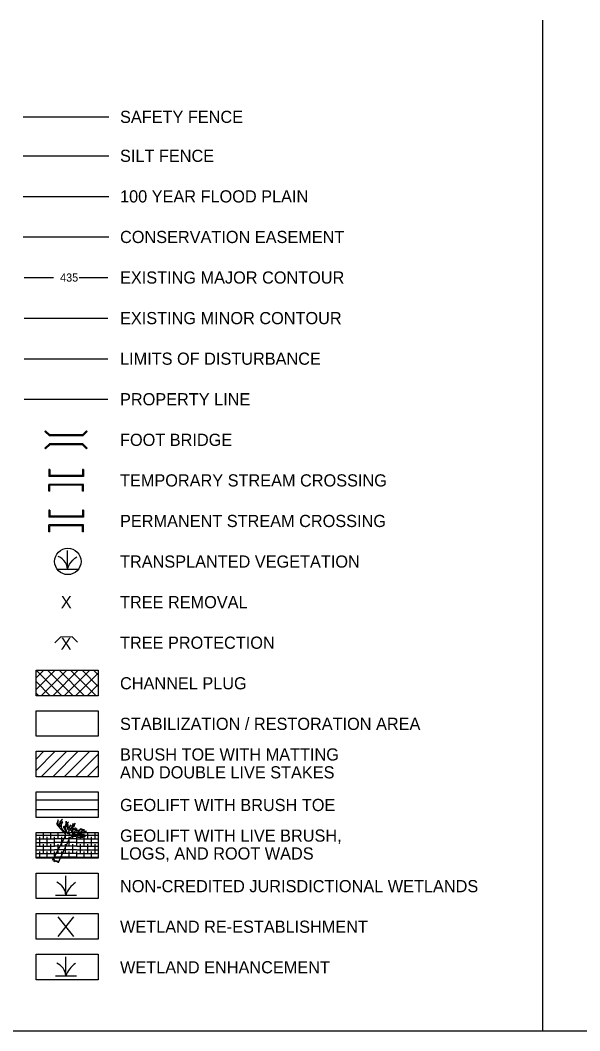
# Model space of a CAD drawing. Extents: x 1577194 to 26153757, y 723342 to 3772486.
# Drawn here: x 1577622 to 1577967, y 724102 to 724725 of the extents above; entities that cross this region are included whole.
import ezdxf

# ---------------------------------------------------------------- set-up
doc = ezdxf.new("R2010")
doc.units = 0
for name, color, linetype in [('Exist Hydro Swamp or Marsh', 7, 'Continuous'), ('G-ANNO-SYMB', 7, 'Continuous'), ('L-CL', 7, 'Continuous')]:
    doc.layers.add(name, color=color, linetype=linetype)

msp = doc.modelspace()

# ---------------------------------------------------------------- linework, layer by layer
at = {"layer": 'Exist Hydro Swamp or Marsh'}
for p, q in [((1577650.61, 724185.77), (1577650.61, 724197.6)), ((1577644.16, 724185.77), (1577650.61, 724185.77)), ((1577650.61, 724185.77), (1577657.06, 724185.77)), ((1577655.6, 724160.25), (1577645.75, 724172.23)), ((1577645.75, 724160.25), (1577655.6, 724172.23)), ((1577650.61, 724135.91), (1577650.61, 724147.75)), ((1577644.16, 724135.91), (1577650.61, 724135.91)), ((1577650.61, 724135.91), (1577657.06, 724135.91))]:
    msp.add_line(p, q, dxfattribs=at)
for centre, radius, start, end in [((1577641.41, 724185.1), 9.22, 4.14034, 67.53497), ((1577664.29, 724181.22), 14.42, 122.12745, 161.62219), ((1577641.41, 724135.24), 9.22, 4.14034, 67.53497), ((1577664.29, 724131.37), 14.42, 122.12745, 161.62219)]:
    msp.add_arc(centre, radius, start, end, dxfattribs=at)
at = {"layer": 'G-ANNO-SYMB'}
for points in [[(1577632.21, 724299.32), (1577670.57, 724299.32), (1577670.57, 724283.55), (1577632.21, 724283.55)], [(1577632.21, 724149.32), (1577670.57, 724149.32), (1577670.57, 724133.55), (1577632.21, 724133.55)]]:
    msp.add_lwpolyline(points, close=True, dxfattribs=at)
at = {"layer": 'L-CL'}
for p, q in [((1577944.13, 724724.8), (1577944.13, 724102.12)), ((1577624.31, 724665.25), (1577677.14, 724665.25)), ((1577624.31, 724641.25), (1577677.14, 724641.25)), ((1577624.31, 724616.25), (1577677.14, 724616.25)), ((1577624.31, 724591.25), (1577677.14, 724591.25)), ((1577624.99, 724566.25), (1577642.9, 724566.25)), ((1577658.73, 724566.25), (1577676.46, 724566.25)), ((1577624.99, 724541.25), (1577676.46, 724541.25)), ((1577624.99, 724516.25), (1577676.46, 724516.25)), ((1577624.99, 724491.25), (1577676.46, 724491.25)), ((1577638.09, 724471.84), (1577637.66, 724471.41)), ((1577640.42, 724468.66), (1577637.66, 724471.41)), ((1577640.67, 724469.27), (1577638.09, 724471.84)), ((1577661.03, 724468.69), (1577640.42, 724468.66)), ((1577660.78, 724469.3), (1577640.67, 724469.27)), ((1577663.35, 724471.88), (1577660.78, 724469.3)), ((1577663.78, 724471.45), (1577661.03, 724468.69)), ((1577663.35, 724471.88), (1577663.78, 724471.45)), ((1577640.43, 724463.8), (1577637.67, 724461.04)), ((1577637.67, 724461.04), (1577638.1, 724460.61)), ((1577640.68, 724463.2), (1577638.1, 724460.61)), ((1577661.03, 724463.83), (1577640.43, 724463.8)), ((1577660.78, 724463.22), (1577640.68, 724463.2)), ((1577663.36, 724460.65), (1577660.78, 724463.22)), ((1577663.79, 724461.08), (1577661.03, 724463.83)), ((1577663.79, 724461.08), (1577663.36, 724460.65)), ((1577640.67, 724447.93), (1577640.07, 724447.93)), ((1577640.07, 724447.93), (1577640.07, 724443.68)), ((1577661.39, 724443.68), (1577640.07, 724443.68)), ((1577640.67, 724447.93), (1577640.67, 724444.28)), ((1577660.78, 724444.28), (1577640.67, 724444.28)), ((1577660.78, 724447.93), (1577660.78, 724444.28)), ((1577661.39, 724447.93), (1577660.78, 724447.93)), ((1577661.39, 724447.93), (1577661.39, 724443.68)), ((1577661.39, 724438.82), (1577640.07, 724438.82)), ((1577640.07, 724434.56), (1577640.07, 724438.82)), ((1577660.78, 724438.21), (1577640.67, 724438.21)), ((1577640.67, 724434.56), (1577640.67, 724438.21)), ((1577660.78, 724434.56), (1577660.78, 724438.21)), ((1577661.39, 724434.56), (1577661.39, 724438.82)), ((1577640.67, 724434.56), (1577640.07, 724434.56)), ((1577661.39, 724434.56), (1577660.78, 724434.56)), ((1577640.67, 724422.93), (1577640.07, 724422.93)), ((1577640.07, 724422.93), (1577640.07, 724418.68)), ((1577661.39, 724418.68), (1577640.07, 724418.68)), ((1577640.67, 724422.93), (1577640.67, 724419.28)), ((1577660.78, 724419.28), (1577640.67, 724419.28)), ((1577660.78, 724422.93), (1577660.78, 724419.28)), ((1577661.39, 724422.93), (1577660.78, 724422.93)), ((1577661.39, 724422.93), (1577661.39, 724418.68)), ((1577661.39, 724413.82), (1577640.07, 724413.82)), ((1577640.07, 724409.56), (1577640.07, 724413.82)), ((1577660.78, 724413.21), (1577640.67, 724413.21)), ((1577640.67, 724409.56), (1577640.67, 724413.21)), ((1577660.78, 724409.56), (1577660.78, 724413.21)), ((1577661.39, 724409.56), (1577661.39, 724413.82)), ((1577640.67, 724409.56), (1577640.07, 724409.56)), ((1577661.39, 724409.56), (1577660.78, 724409.56)), ((1577632.21, 724319.52), (1577637.01, 724324.32)), ((1577632.21, 724312.45), (1577644.08, 724324.32)), ((1577632.26, 724324.32), (1577648.03, 724308.55)), ((1577635.39, 724308.55), (1577651.15, 724324.32)), ((1577639.33, 724324.32), (1577655.1, 724308.55)), ((1577642.46, 724308.55), (1577658.22, 724324.32)), ((1577646.4, 724324.32), (1577662.17, 724308.55)), ((1577649.53, 724308.55), (1577665.29, 724324.32)), ((1577653.47, 724324.32), (1577669.24, 724308.55)), ((1577660.54, 724324.32), (1577670.57, 724314.29)), ((1577667.61, 724324.32), (1577670.57, 724321.36)), ((1577656.6, 724308.55), (1577670.57, 724322.52)), ((1577632.21, 724317.3), (1577640.96, 724308.55)), ((1577663.67, 724308.55), (1577670.57, 724315.45)), ((1577632.21, 724310.22), (1577633.88, 724308.55)), ((1577632.21, 724269.52), (1577637.01, 724274.32)), ((1577632.21, 724262.45), (1577644.08, 724274.32)), ((1577635.39, 724258.55), (1577651.15, 724274.32)), ((1577642.46, 724258.55), (1577658.22, 724274.32)), ((1577649.53, 724258.55), (1577665.29, 724274.32)), ((1577656.6, 724258.55), (1577670.57, 724272.52)), ((1577663.67, 724258.55), (1577670.57, 724265.45)), ((1577632.21, 724244.43), (1577670.57, 724244.43)), ((1577632.21, 724238.43), (1577670.57, 724238.43)), ((1577645.94, 724232.07), (1577645.11, 724229.58)), ((1577645.82, 724229.4), (1577645.94, 724232.07)), ((1577646.83, 724230.94), (1577646.66, 724229.5)), ((1577648.59, 724232.43), (1577646.83, 724230.94)), ((1577647.19, 724229.65), (1577647.69, 724231.29)), ((1577648.75, 724230.86), (1577647.19, 724229.65)), ((1577647.69, 724231.29), (1577648.59, 724232.43)), ((1577647.82, 724229.22), (1577648.75, 724230.86)), ((1577650.75, 724231.36), (1577650.32, 724228.69)), ((1577650.95, 724229.61), (1577650.75, 724231.36)), ((1577650.75, 724228.71), (1577652.16, 724230.75)), ((1577652.16, 724230.75), (1577650.95, 724229.61)), ((1577632.28, 724220.47), (1577632.28, 724224.32)), ((1577636.78, 724220.47), (1577636.78, 724224.32)), ((1577641.28, 724220.47), (1577641.28, 724224.32)), ((1577645.87, 724228.12), (1577645.11, 724229.58)), ((1577647.35, 724227.78), (1577645.82, 724229.4)), ((1577645.87, 724228.12), (1577647.78, 724226.13)), ((1577645.91, 724220.5), (1577645.91, 724224.32)), ((1577646.66, 724229.5), (1577647.35, 724227.78)), ((1577647.78, 724226.13), (1577648.71, 724225)), ((1577647.92, 724227.02), (1577647.82, 724229.22)), ((1577649.38, 724225.39), (1577647.92, 724227.02)), ((1577648.71, 724225), (1577650.11, 724223.49)), ((1577649.75, 724227.42), (1577649, 724227.84)), ((1577649, 724227.84), (1577650.27, 724225.61)), ((1577650.54, 724224.12), (1577649.38, 724225.39)), ((1577649.8, 724228.48), (1577649.75, 724227.42)), ((1577650.21, 724226.58), (1577649.8, 724228.48)), ((1577650.32, 724228.69), (1577650.21, 724226.58)), ((1577650.27, 724225.61), (1577650.54, 724224.12)), ((1577650.41, 724220.5), (1577650.41, 724224.32)), ((1577650.64, 724226.6), (1577650.75, 724228.71)), ((1577651.7, 724223.17), (1577650.64, 724226.6)), ((1577652.06, 724229.18), (1577651.47, 724228.43)), ((1577651.47, 724228.43), (1577651.62, 724226.63)), ((1577651.62, 724226.63), (1577652.59, 724225.8)), ((1577652.59, 724225.8), (1577651.7, 724223.17)), ((1577651.97, 724227.7), (1577652.06, 724229.18)), ((1577652.78, 724226.75), (1577651.97, 724227.7)), ((1577653.64, 724229.1), (1577652.75, 724227.93)), ((1577652.75, 724227.93), (1577652.78, 724226.75)), ((1577652.82, 724224.11), (1577655.31, 724224.93)), ((1577653.1, 724227.54), (1577653.64, 724229.1)), ((1577653.54, 724225.61), (1577653.1, 724227.54)), ((1577654.2, 724228.02), (1577653.54, 724225.61)), ((1577653.92, 724225.04), (1577655, 724226.15)), ((1577655.31, 724224.93), (1577653.92, 724225.04)), ((1577655.05, 724229.75), (1577654.2, 724228.02)), ((1577654.23, 724226.38), (1577654.49, 724227.43)), ((1577656.42, 724226.87), (1577654.23, 724226.38)), ((1577654.49, 724227.43), (1577655.7, 724228.29)), ((1577654.91, 724220.5), (1577654.91, 724224.32)), ((1577656.35, 724230.05), (1577654.98, 724228.25)), ((1577654.98, 724228.25), (1577655.05, 724229.75)), ((1577655, 724226.15), (1577657.42, 724226.41)), ((1577655.5, 724222.95), (1577656.85, 724224.57)), ((1577655.7, 724228.29), (1577656.35, 724230.05)), ((1577656.4, 724225.5), (1577655.73, 724224.18)), ((1577657.56, 724226.16), (1577656.4, 724225.5)), ((1577657.42, 724226.41), (1577656.42, 724226.87)), ((1577656.85, 724224.57), (1577658.53, 724224.88)), ((1577656.93, 724225.14), (1577657.56, 724226.16)), ((1577658.72, 724225.83), (1577656.93, 724225.14)), ((1577658.53, 724224.88), (1577659.43, 724225.96)), ((1577659.58, 724226.63), (1577658.72, 724225.83)), ((1577660.24, 724225.01), (1577658.97, 724223.95)), ((1577659.43, 724225.96), (1577660.55, 724226.35)), ((1577659.56, 724220.47), (1577659.56, 724224.32)), ((1577660.55, 724226.35), (1577659.58, 724226.63)), ((1577660.82, 724225.85), (1577660.24, 724225.01)), ((1577660.49, 724224.14), (1577662, 724224.42)), ((1577662.16, 724226.01), (1577660.82, 724225.85)), ((1577661.35, 724224.94), (1577661.68, 724225.64)), ((1577663.33, 724225.12), (1577661.35, 724224.94)), ((1577661.68, 724225.64), (1577662.16, 724226.01)), ((1577662, 724224.42), (1577663.33, 724225.12)), ((1577664.06, 724220.47), (1577664.06, 724224.32)), ((1577668.56, 724220.47), (1577668.56, 724224.32)), ((1577632.21, 724222.72), (1577643.53, 724222.72)), ((1577632.21, 724220.47), (1577643.53, 724220.47)), ((1577632.21, 724218.22), (1577643.53, 724218.22)), ((1577634.53, 724215.97), (1577634.53, 724221.6)), ((1577639.03, 724215.97), (1577639.03, 724221.6)), ((1577643.66, 724222.75), (1577657.16, 724222.75)), ((1577643.66, 724216), (1577643.66, 724221.63)), ((1577643.66, 724220.5), (1577657.16, 724220.5)), ((1577643.66, 724218.25), (1577657.16, 724218.25)), ((1577650.28, 724222.54), (1577643.69, 724209.52)), ((1577646.51, 724206.9), (1577653.13, 724221.09)), ((1577648.16, 724216), (1577648.16, 724221.63)), ((1577650.11, 724223.49), (1577650.28, 724222.54)), ((1577652.66, 724216), (1577652.66, 724221.63)), ((1577652.91, 724222.57), (1577652.82, 724224.11)), ((1577654.49, 724222.95), (1577652.91, 724222.57)), ((1577653.13, 724221.09), (1577654.39, 724222.02)), ((1577654.39, 724222.02), (1577656.31, 724222)), ((1577655.73, 724224.18), (1577654.49, 724222.95)), ((1577656.87, 724222.93), (1577655.5, 724222.95)), ((1577656.31, 724222), (1577657.89, 724221.38)), ((1577658.97, 724223.95), (1577656.87, 724222.93)), ((1577657.31, 724222.72), (1577670.57, 724222.72)), ((1577657.31, 724215.97), (1577657.31, 724221.6)), ((1577657.31, 724220.47), (1577670.57, 724220.47)), ((1577657.31, 724218.22), (1577670.57, 724218.22)), ((1577657.48, 724222.13), (1577658.66, 724223.17)), ((1577658.64, 724222.25), (1577657.48, 724222.13)), ((1577657.89, 724221.38), (1577661.09, 724221.42)), ((1577659.38, 724222.75), (1577658.64, 724222.25)), ((1577658.66, 724223.17), (1577660.49, 724224.14)), ((1577660.39, 724223.21), (1577659.38, 724222.75)), ((1577659.68, 724222.08), (1577660.47, 724222.77)), ((1577661, 724221.86), (1577659.68, 724222.08)), ((1577662.06, 724223.06), (1577660.39, 724223.21)), ((1577660.47, 724222.77), (1577662.06, 724223.06)), ((1577662.61, 724222.06), (1577661, 724221.86)), ((1577661.09, 724221.42), (1577662.61, 724222.06)), ((1577661.81, 724215.97), (1577661.81, 724221.6)), ((1577666.31, 724215.97), (1577666.31, 724221.6)), ((1577632.21, 724215.97), (1577643.53, 724215.97)), ((1577632.21, 724213.69), (1577643.53, 724213.69)), ((1577632.28, 724215.97), (1577632.28, 724217.1)), ((1577632.28, 724211.44), (1577632.28, 724215.94)), ((1577634.53, 724208.55), (1577634.53, 724212.57)), ((1577636.78, 724215.97), (1577636.78, 724217.1)), ((1577636.78, 724211.44), (1577636.78, 724215.94)), ((1577639.03, 724208.55), (1577639.03, 724212.57)), ((1577641.28, 724215.97), (1577641.28, 724217.1)), ((1577641.28, 724211.44), (1577641.28, 724215.94)), ((1577643.66, 724216), (1577657.16, 724216)), ((1577643.66, 724213.72), (1577657.16, 724213.72)), ((1577643.66, 724208.55), (1577643.66, 724212.59)), ((1577645.91, 724216), (1577645.91, 724217.13)), ((1577645.91, 724211.47), (1577645.91, 724215.97)), ((1577648.16, 724208.55), (1577648.16, 724212.59)), ((1577650.41, 724216), (1577650.41, 724217.13)), ((1577650.41, 724211.47), (1577650.41, 724215.97)), ((1577652.66, 724208.55), (1577652.66, 724212.59)), ((1577654.91, 724216), (1577654.91, 724217.13)), ((1577654.91, 724211.47), (1577654.91, 724215.97)), ((1577657.31, 724215.97), (1577670.57, 724215.97)), ((1577657.31, 724213.69), (1577670.57, 724213.69)), ((1577657.31, 724208.55), (1577657.31, 724212.57)), ((1577659.56, 724215.97), (1577659.56, 724217.1)), ((1577659.56, 724211.44), (1577659.56, 724215.94)), ((1577661.81, 724208.55), (1577661.81, 724212.57)), ((1577664.06, 724215.97), (1577664.06, 724217.1)), ((1577664.06, 724211.44), (1577664.06, 724215.94)), ((1577666.31, 724208.55), (1577666.31, 724212.57)), ((1577668.56, 724215.97), (1577668.56, 724217.1)), ((1577668.56, 724211.44), (1577668.56, 724215.94)), ((1577632.21, 724211.44), (1577643.53, 724211.44)), ((1577632.21, 724209.19), (1577643.53, 724209.19)), ((1577642.27, 724207.23), (1577643.69, 724209.52)), ((1577643.43, 724207.93), (1577642.27, 724207.23)), ((1577643.18, 724206.96), (1577643.43, 724207.93)), ((1577643.7, 724207.43), (1577643.18, 724206.96)), ((1577643.37, 724206.26), (1577643.7, 724207.43)), ((1577644.15, 724206.71), (1577643.37, 724206.26)), ((1577643.66, 724211.47), (1577657.16, 724211.47)), ((1577643.66, 724209.22), (1577657.16, 724209.22)), ((1577644.81, 724206.77), (1577644.15, 724206.71)), ((1577644.42, 724206.21), (1577644.81, 724206.77)), ((1577645.59, 724206.55), (1577644.42, 724206.21)), ((1577645.81, 724205.66), (1577645.59, 724206.55)), ((1577646.51, 724206.9), (1577645.81, 724205.66)), ((1577657.31, 724211.44), (1577670.57, 724211.44)), ((1577657.31, 724209.19), (1577670.57, 724209.19)), ((1577194.13, 724102.12), (1578789.48, 724102.12))]:
    msp.add_line(p, q, dxfattribs=at)
for points in [[(1577651.65, 724386.63), (1577651.35, 724388.01), (1577650.96, 724389.39), (1577650.27, 724390.67), (1577649.39, 724391.85), (1577648.4, 724392.94), (1577647.22, 724393.72), (1577645.94, 724394.41)], [(1577651.65, 724386.63), (1577651.65, 724398.15)], [(1577651.65, 724386.63), (1577652.24, 724388.11), (1577652.93, 724389.59), (1577653.81, 724390.96), (1577654.9, 724392.15), (1577656.08, 724393.23), (1577657.36, 724394.21)], [(1577645.45, 724386.63), (1577657.95, 724386.63)], [(1577657.71, 724341.6), (1577654.45, 724344.8), (1577647.25, 724344.74), (1577643.75, 724341.15)]]:
    msp.add_lwpolyline(points, dxfattribs=at)
for points in [[(1577632.21, 724324.32), (1577670.57, 724324.32), (1577670.57, 724308.55), (1577632.21, 724308.55)], [(1577632.21, 724299.32), (1577670.57, 724299.32), (1577670.57, 724283.55), (1577632.21, 724283.55)], [(1577632.21, 724274.32), (1577670.57, 724274.32), (1577670.57, 724258.55), (1577632.21, 724258.55)], [(1577632.21, 724249.32), (1577670.57, 724249.32), (1577670.57, 724233.55), (1577632.21, 724233.55)], [(1577632.21, 724224.32), (1577670.57, 724224.32), (1577670.57, 724208.55), (1577632.21, 724208.55)], [(1577632.21, 724224.32), (1577670.57, 724224.32), (1577670.57, 724208.55), (1577632.21, 724208.55)], [(1577632.21, 724199.32), (1577670.57, 724199.32), (1577670.57, 724183.55), (1577632.21, 724183.55)], [(1577632.21, 724174.32), (1577670.57, 724174.32), (1577670.57, 724158.55), (1577632.21, 724158.55)], [(1577632.21, 724149.32), (1577670.57, 724149.32), (1577670.57, 724133.55), (1577632.21, 724133.55)]]:
    msp.add_lwpolyline(points, close=True, dxfattribs=at)
msp.add_circle((1577651.81, 724391.3), 8.12, dxfattribs=at)

# ---------------------------------------------------------------- texts
for s, height, p in [('SAFETY FENCE', 7.5, (1577683.96, 724661.5)), ('SILT FENCE', 7.5, (1577683.96, 724637.5)), ('100 YEAR FLOOD PLAIN', 7.5, (1577683.96, 724612.5)), ('CONSERVATION EASEMENT', 7.5, (1577683.96, 724587.5)), ('435', 5, (1577647.03, 724563.75)), ('EXISTING MAJOR CONTOUR', 7.5, (1577683.96, 724562.5)), ('EXISTING MINOR CONTOUR', 7.5, (1577683.96, 724537.5)), ('LIMITS OF DISTURBANCE', 7.5, (1577683.96, 724512.5)), ('PROPERTY LINE', 7.5, (1577683.96, 724487.5)), ('FOOT BRIDGE', 7.5, (1577683.96, 724462.5)), ('TEMPORARY STREAM CROSSING', 7.5, (1577683.96, 724437.5)), ('PERMANENT STREAM CROSSING', 7.5, (1577683.96, 724412.5)), ('TRANSPLANTED VEGETATION', 7.5, (1577683.96, 724387.5)), ('X', 7.5, (1577647.5, 724362.5)), ('TREE REMOVAL', 7.5, (1577683.96, 724362.5)), ('X', 7.5, (1577647.36, 724336.94)), ('TREE PROTECTION', 7.5, (1577683.96, 724337.5)), ('CHANNEL PLUG', 7.5, (1577683.96, 724312.5)), ('STABILIZATION / RESTORATION AREA', 7.5, (1577683.96, 724287.5)), ('BRUSH TOE WITH MATTING', 7.5, (1577683.96, 724268.64)), ('AND DOUBLE LIVE STAKES', 7.5, (1577683.96, 724257.63)), ('GEOLIFT WITH BRUSH TOE', 7.5, (1577683.96, 724237.5)), ('GEOLIFT WITH LIVE BRUSH,', 7.5, (1577683.96, 724218.64)), ('LOGS, AND ROOT WADS', 7.5, (1577683.96, 724207.63)), ('NON-CREDITED JURISDICTIONAL WETLANDS', 7.5, (1577683.96, 724187.5)), ('WETLAND RE-ESTABLISHMENT', 7.5, (1577683.96, 724162.5)), ('WETLAND ENHANCEMENT', 7.5, (1577683.96, 724137.5))]:
    msp.add_text(s, height=height, dxfattribs=at).set_placement(p)

doc.saveas('drawing.dxf')
